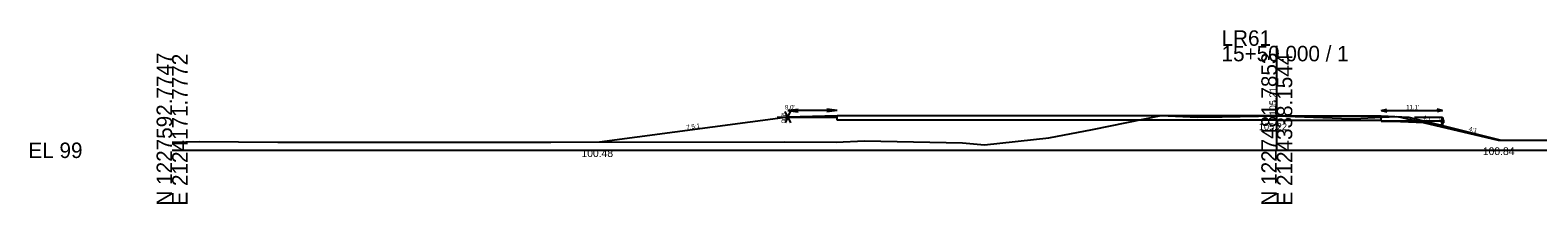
# Model space of a CAD drawing. Extents: x -26 to 1403, y -10 to 9574.
# Drawn here: x 974.3 to 1247.3, y 5490.3 to 5521.7 of the extents above; entities that cross this region are included whole.
import ezdxf

# ---------------------------------------------------------------- set-up
doc = ezdxf.new("R2010")
doc.units = 0
for name, color, linetype in [('XS_CELL', 7, 'Continuous'), ('XS_P_FINISHED_GRADE', 7, 'Continuous'), ('XS_P_FINISHED_GRADE_ELEV_TX', 7, 'Continuous'), ('XS_P_SUBGRADE_GRANULAR', 7, 'Continuous'), ('XS_P_SUBGRADE_PAVEMENT', 7, 'Continuous'), ('XS_P_TX_CLEARZONE', 7, 'Continuous'), ('XS_P_TX_DCH', 7, 'Continuous'), ('XS_P_TX_FS_BS', 7, 'Continuous'), ('XS_X_GROUND', 7, 'Continuous'), ('XS_X_GROUND_TX', 7, 'Continuous')]:
    doc.layers.add(name, color=color, linetype=linetype)

msp = doc.modelspace()

# ---------------------------------------------------------------- linework, layer by layer
at = {"layer": 'XS_CELL'}
for p, q in [((1200, 5500), (1200, 5518.91)), ((1000, 5500), (1200, 5500)), ((1200, 5500), (1400, 5500))]:
    msp.add_line(p, q, dxfattribs=at)
at = {"layer": 'XS_P_FINISHED_GRADE'}
for p, q in [((1111.46, 5506), (1077.41, 5501.48)), ((1120.43, 5506.21), (1111.46, 5506)), ((1200, 5506.21), (1120.43, 5506.21)), ((1200, 5506.21), (1218.92, 5506.21)), ((1218.92, 5506.21), (1223.92, 5506.01)), ((1223.92, 5506.01), (1230, 5504.49)), ((1230, 5504.49), (1240.6, 5501.84))]:
    msp.add_line(p, q, dxfattribs=at)
at = {"layer": 'XS_P_SUBGRADE_GRANULAR'}
for p, q in [((1111.08, 5506), (1120.43, 5506)), ((1120.43, 5506), (1118.43, 5506)), ((1230.2, 5505.25), (1218.92, 5505.25)), ((1218.92, 5505.25), (1220.92, 5505.25)), ((1220.92, 5505.25), (1228.11, 5504.96))]:
    msp.add_line(p, q, dxfattribs=at)
at = {"layer": 'XS_P_SUBGRADE_PAVEMENT'}
for p, q in [((1120.43, 5505.46), (1120.43, 5506.21)), ((1200, 5505.46), (1120.43, 5505.46)), ((1200, 5505.46), (1218.92, 5505.46)), ((1218.92, 5505.46), (1218.92, 5506.21))]:
    msp.add_line(p, q, dxfattribs=at)
at = {"layer": 'XS_P_TX_CLEARZONE'}
for p, q in [((1109.57, 5506), (1111.46, 5506)), ((1111.46, 5506), (1110.99, 5507)), ((1111.46, 5506), (1110.99, 5505)), ((1111.46, 5507.21), (1113.34, 5507.46)), ((1111.46, 5507.21), (1113.34, 5506.96)), ((1120.43, 5507.21), (1111.46, 5507.21)), ((1111.46, 5506), (1111.93, 5507)), ((1111.46, 5506), (1111.93, 5505)), ((1120.43, 5507.21), (1118.55, 5507.46)), ((1120.43, 5507.21), (1118.55, 5506.96)), ((1218.92, 5507.21), (1219.92, 5507.46)), ((1218.92, 5507.21), (1219.92, 5506.96)), ((1218.92, 5507.21), (1230, 5507.21)), ((1224.92, 5506.01), (1230, 5506.01)), ((1230, 5507.21), (1229, 5507.46)), ((1230, 5507.21), (1229, 5506.96)), ((1230, 5506.01), (1229.75, 5505.01)), ((1230, 5504.49), (1229.75, 5505.49)), ((1230, 5506.01), (1230, 5504.49)), ((1230, 5506.01), (1230.25, 5505.01)), ((1230, 5504.49), (1230.25, 5505.49))]:
    msp.add_line(p, q, dxfattribs=at)
at = {"layer": 'XS_X_GROUND'}
for p, q in [((1166.66, 5503.75), (1179.05, 5506.3)), ((1179.05, 5506.3), (1180.33, 5506.25)), ((1180.33, 5506.25), (1185.66, 5505.99)), ((1185.66, 5505.99), (1190.12, 5506.07)), ((1190.12, 5506.07), (1199.92, 5506.22)), ((1199.92, 5506.22), (1211.74, 5505.84)), ((1211.74, 5505.84), (1213.96, 5505.78)), ((1213.96, 5505.78), (1221.63, 5506.1)), ((1221.63, 5506.1), (1222.4, 5505.99)), ((1222.4, 5505.99), (1240.1, 5501.84)), ((1158.75, 5502.27), (1166.66, 5503.75)), ((1000, 5501.48), (1004.88, 5501.57)), ((1004.88, 5501.57), (1019.16, 5501.5)), ((1019.16, 5501.5), (1062.71, 5501.47)), ((1062.71, 5501.47), (1066.49, 5501.46)), ((1066.49, 5501.46), (1068.57, 5501.46)), ((1068.57, 5501.46), (1110.87, 5501.54)), ((1110.87, 5501.54), (1120.22, 5501.48)), ((1120.22, 5501.48), (1125.33, 5501.69)), ((1125.33, 5501.69), (1143.12, 5501.37)), ((1143.12, 5501.37), (1147.08, 5500.96)), ((1147.08, 5500.96), (1158.75, 5502.27)), ((1240.1, 5501.84), (1284.45, 5501.87))]:
    msp.add_line(p, q, dxfattribs=at)

# ---------------------------------------------------------------- texts
at = {"layer": 'XS_CELL'}
for s, p in [('15+50.000 / 1', (1190, 5516.11)), ('LR61', (1190, 5518.91)), ('EL 99', (974, 5498.6))]:
    msp.add_text(s, height=2.8, dxfattribs=at).set_placement(p)
for s, p in [('N 1227592.7747', (1000, 5490)), ('E 2124171.7772', (1002.8, 5490)), ('N 1227481.7853', (1200, 5490)), ('E 2124338.1544', (1202.8, 5490))]:
    msp.add_text(s, height=2.8, rotation=90, dxfattribs=at).set_placement(p)
at = {"layer": 'XS_P_FINISHED_GRADE_ELEV_TX'}
msp.add_text('105.21', height=1.25, rotation=90, dxfattribs=at).set_placement((1199.92, 5506.3))
at = {"layer": 'XS_P_TX_CLEARZONE'}
for s, p in [("9.0'", (1110.96, 5507.41)), ("11.1'", (1223.41, 5507.41))]:
    msp.add_text(s, height=0.8, dxfattribs=at).set_placement(p)
for s, p in [("0.0'", (1111.08, 5504.94)), ("1.5'", (1230.2, 5504.36))]:
    msp.add_text(s, height=0.8, rotation=90, dxfattribs=at).set_placement(p)
at = {"layer": 'XS_P_TX_DCH'}
for s, p in [('100.48', (1074.11, 5498.78)), ('100.84', (1237.3, 5499.14))]:
    msp.add_text(s, height=1.4, dxfattribs=at).set_placement(p)
at = {"layer": 'XS_P_TX_FS_BS'}
for s, rotation, p in [('1:0', 90, (1111.26, 5505.29)), ('4:1', 345.9638, (1226.35, 5505.61)), ('7.5:1', 7.5658, (1093.16, 5503.77)), ('4:1', 345.9638, (1234.69, 5503.53))]:
    msp.add_text(s, height=0.8, rotation=rotation, dxfattribs=at).set_placement(p)
at = {"layer": 'XS_X_GROUND_TX'}
msp.add_text('105.22', height=1.25, rotation=360, dxfattribs=at).set_placement((1196.74, 5503.64))

doc.saveas('drawing.dxf')
